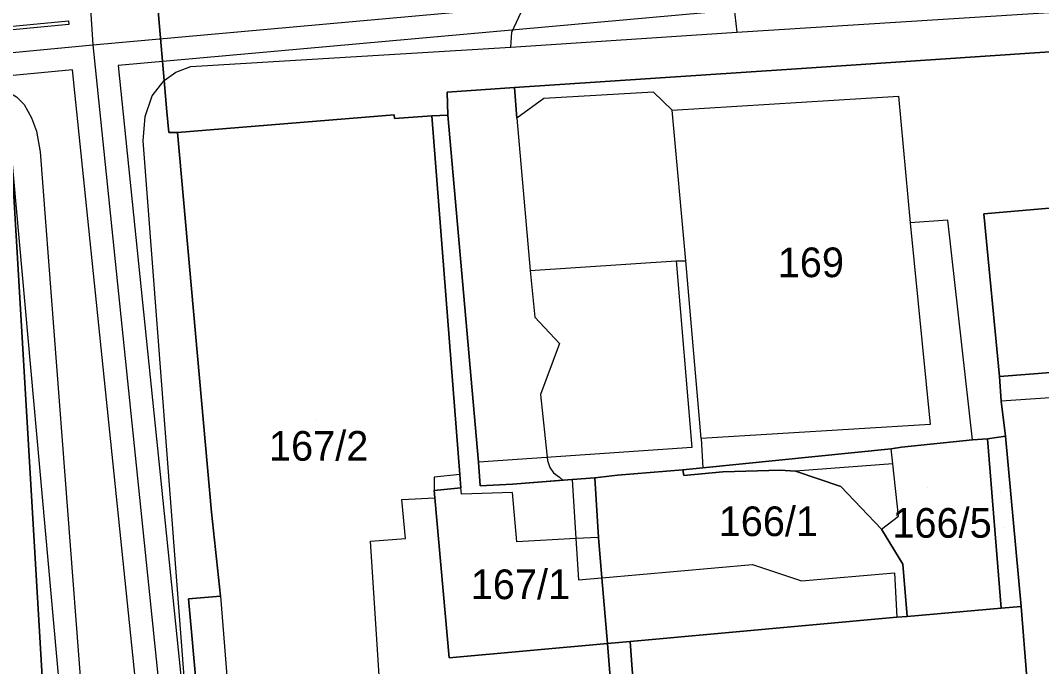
# Model space of a CAD drawing. Extents: x -263423 to -261326, y -1240067 to -1237864.
# Drawn here: x -262906.4 to -262837.6, y -1239995.6 to -1239952.1 of the extents above; entities that cross this region are included whole.
import ezdxf

# ---------------------------------------------------------------- set-up
doc = ezdxf.new("R2010")
doc.units = 0
for name, color, linetype in [('body_kn', 7, 'Continuous'), ('kladpar_druhypozemkov', 7, 'Continuous'), ('kladpar_hranice', 7, 'Continuous'), ('kladpar_parcelnecisla', 7, 'Continuous'), ('kladpar_plochy', 7, 'Continuous'), ('kladpar_sipky', 7, 'Continuous'), ('tarchy_linie', 7, 'Continuous'), ('zappar_hrandruhpozemk', 7, 'Continuous')]:
    doc.layers.add(name, color=color, linetype=linetype)

msp = doc.modelspace()

# ---------------------------------------------------------------- linework, layer by layer
at = {"layer": 'body_kn'}
for p, q in [((-262903.16, -1239952.09), (-262903.16, -1239952.09)), ((-262903.16, -1239952.09), (-262903.16, -1239952.09)), ((-262903.14, -1239952.33), (-262903.14, -1239952.33)), ((-262873.29, -1239952.85), (-262873.29, -1239952.85)), ((-262858.12, -1239952.85), (-262858.12, -1239952.85)), ((-262858.12, -1239952.85), (-262858.12, -1239952.85)), ((-262901.51, -1239953.72), (-262901.51, -1239953.72)), ((-262873.36, -1239953.87), (-262873.36, -1239953.87)), ((-262873.36, -1239953.87), (-262873.36, -1239953.87)), ((-262902.88, -1239955.4), (-262902.88, -1239955.4)), ((-262899.82, -1239955.11), (-262899.82, -1239955.11)), ((-262894.91, -1239955.17), (-262894.91, -1239955.17)), ((-262854.44, -1239955.35), (-262854.44, -1239955.35)), ((-262854.44, -1239955.35), (-262854.44, -1239955.35)), ((-262896.7, -1239956.12), (-262896.7, -1239956.12)), ((-262896.7, -1239956.12), (-262896.7, -1239956.12)), ((-262895.93, -1239955.55), (-262895.93, -1239955.55)), ((-262877.64, -1239956.91), (-262877.64, -1239956.91)), ((-262877.64, -1239956.91), (-262877.64, -1239956.91)), ((-262873.11, -1239956.58), (-262873.11, -1239956.58)), ((-262863.75, -1239956.9), (-262863.75, -1239956.9)), ((-262897.53, -1239957.14), (-262897.53, -1239957.14)), ((-262871.14, -1239957.32), (-262871.14, -1239957.32)), ((-262847.24, -1239957.17), (-262847.24, -1239957.17)), ((-262906.14, -1239957.73), (-262906.14, -1239957.73)), ((-262896.52, -1239958.22), (-262896.52, -1239958.22)), ((-262862.48, -1239958.12), (-262862.48, -1239958.12)), ((-262905.64, -1239958.63), (-262905.64, -1239958.63)), ((-262897.99, -1239958.54), (-262897.99, -1239958.54)), ((-262881.22, -1239958.42), (-262881.22, -1239958.42)), ((-262881.22, -1239958.42), (-262881.22, -1239958.42)), ((-262881.2, -1239958.68), (-262881.2, -1239958.68)), ((-262878.67, -1239958.5), (-262878.67, -1239958.5)), ((-262877.59, -1239958.44), (-262877.59, -1239958.44)), ((-262872.94, -1239958.65), (-262872.94, -1239958.65)), ((-262872.94, -1239958.65), (-262872.94, -1239958.65)), ((-262905.32, -1239959.52), (-262905.32, -1239959.52)), ((-262896.4, -1239959.63), (-262896.4, -1239959.63)), ((-262895.82, -1239959.63), (-262895.82, -1239959.63)), ((-262898.12, -1239960.19), (-262898.12, -1239960.19)), ((-262905.07, -1239960.93), (-262905.07, -1239960.93)), ((-262841.48, -1239965.1), (-262841.48, -1239965.1)), ((-262846.45, -1239965.71), (-262846.45, -1239965.71)), ((-262843.9, -1239965.53), (-262843.9, -1239965.53)), ((-262862.21, -1239968.26), (-262862.21, -1239968.26)), ((-262861.57, -1239968.26), (-262861.57, -1239968.26)), ((-262861.57, -1239968.26), (-262861.57, -1239968.26)), ((-262872.05, -1239968.91), (-262872.05, -1239968.91)), ((-262872.05, -1239968.91), (-262872.05, -1239968.91)), ((-262871.73, -1239972.06), (-262871.73, -1239972.06)), ((-262870.08, -1239973.83), (-262870.08, -1239973.83)), ((-262840.44, -1239976.07), (-262840.44, -1239976.07)), ((-262871.35, -1239977.27), (-262871.35, -1239977.27)), ((-262840.32, -1239977.72), (-262840.32, -1239977.72)), ((-262845.11, -1239979.3), (-262845.11, -1239979.3)), ((-262860.54, -1239980.25), (-262860.54, -1239980.25)), ((-262860.54, -1239980.25), (-262860.54, -1239980.25)), ((-262841.23, -1239980.27), (-262841.23, -1239980.27)), ((-262840.02, -1239980.08), (-262840.02, -1239980.08)), ((-262861.17, -1239980.84), (-262861.17, -1239980.84)), ((-262847.73, -1239980.94), (-262847.73, -1239980.94)), ((-262847.03, -1239980.82), (-262847.03, -1239980.82)), ((-262842.25, -1239980.33), (-262842.25, -1239980.33)), ((-262842.25, -1239980.33), (-262842.25, -1239980.33)), ((-262875.54, -1239981.83), (-262875.54, -1239981.83)), ((-262870.89, -1239981.73), (-262870.89, -1239981.73)), ((-262870.73, -1239982.19), (-262870.73, -1239982.19)), ((-262861.76, -1239982.35), (-262861.76, -1239982.35)), ((-262860.42, -1239982.22), (-262860.42, -1239982.22)), ((-262855.2, -1239982.37), (-262855.2, -1239982.37)), ((-262855.2, -1239982.37), (-262855.2, -1239982.37)), ((-262847.61, -1239981.96), (-262847.61, -1239981.96)), ((-262878.53, -1239982.84), (-262878.53, -1239982.84)), ((-262876.8, -1239982.66), (-262876.8, -1239982.66)), ((-262876.8, -1239982.66), (-262876.8, -1239982.66)), ((-262870.47, -1239982.55), (-262870.47, -1239982.55)), ((-262870.08, -1239982.86), (-262870.08, -1239982.86)), ((-262869.22, -1239983.01), (-262869.22, -1239983.01)), ((-262869.22, -1239983.01), (-262869.22, -1239983.01)), ((-262867.69, -1239982.89), (-262867.69, -1239982.89)), ((-262866.16, -1239982.71), (-262866.16, -1239982.71)), ((-262861.7, -1239982.73), (-262861.7, -1239982.73)), ((-262859.08, -1239982.48), (-262859.08, -1239982.48)), ((-262856.73, -1239982.43), (-262856.73, -1239982.43)), ((-262854.18, -1239982.44), (-262854.18, -1239982.44)), ((-262878.53, -1239983.74), (-262878.53, -1239983.74)), ((-262876.72, -1239983.56), (-262876.72, -1239983.56)), ((-262875.41, -1239983.43), (-262875.41, -1239983.43)), ((-262873.24, -1239983.31), (-262873.24, -1239983.31)), ((-262869.84, -1239983.06), (-262869.84, -1239983.06)), ((-262851.12, -1239983.48), (-262851.12, -1239983.48)), ((-262880.7, -1239984.36), (-262880.7, -1239984.36)), ((-262878.47, -1239984.25), (-262878.47, -1239984.25)), ((-262876.68, -1239984), (-262876.68, -1239984)), ((-262873.24, -1239983.89), (-262873.24, -1239983.89)), ((-262893.52, -1239985.2), (-262893.52, -1239985.2)), ((-262847.24, -1239985.47), (-262847.24, -1239985.47)), ((-262848.39, -1239986.36), (-262848.39, -1239986.36)), ((-262848.39, -1239986.36), (-262848.39, -1239986.36)), ((-262882.82, -1239987.16), (-262882.82, -1239987.16)), ((-262880.46, -1239986.98), (-262880.46, -1239986.98)), ((-262868.97, -1239986.99), (-262868.97, -1239986.99)), ((-262868.97, -1239986.99), (-262868.97, -1239986.99)), ((-262867.45, -1239986.91), (-262867.45, -1239986.91)), ((-262867.45, -1239986.91), (-262867.45, -1239986.91)), ((-262872.94, -1239987.2), (-262872.94, -1239987.2)), ((-262857.07, -1239988.74), (-262857.07, -1239988.74)), ((-262846.94, -1239988.72), (-262846.94, -1239988.72)), ((-262868.8, -1239989.77), (-262868.8, -1239989.77)), ((-262867.22, -1239989.63), (-262867.22, -1239989.63)), ((-262867.22, -1239989.63), (-262867.22, -1239989.63)), ((-262853.76, -1239989.84), (-262853.76, -1239989.84)), ((-262847.51, -1239989.29), (-262847.51, -1239989.29)), ((-262895.07, -1239991.06), (-262895.07, -1239991.06)), ((-262892.91, -1239990.88), (-262892.91, -1239990.88)), ((-262892.91, -1239990.88), (-262892.91, -1239990.88)), ((-262840.32, -1239991.68), (-262840.32, -1239991.68)), ((-262838.98, -1239991.56), (-262838.98, -1239991.56)), ((-262838.98, -1239991.56), (-262838.98, -1239991.56)), ((-262847.34, -1239992.29), (-262847.34, -1239992.29)), ((-262847.34, -1239992.29), (-262847.34, -1239992.29)), ((-262846.64, -1239992.23), (-262846.64, -1239992.23)), ((-262866.85, -1239994.05), (-262866.85, -1239994.05)), ((-262865.32, -1239993.93), (-262865.32, -1239993.93)), ((-262877.5, -1239995.02), (-262877.5, -1239995.02))]:
    msp.add_line(p, q, dxfattribs=at)
at = {"layer": 'kladpar_druhypozemkov'}
for p, q in [((-262853.98, -1239966.97), (-262853.98, -1239966.97)), ((-262886.48, -1239979.04), (-262886.48, -1239979.04)), ((-262845.26, -1239983.53), (-262845.26, -1239983.53)), ((-262840.38, -1239983.87), (-262840.38, -1239983.87)), ((-262856.3, -1239984.84), (-262856.3, -1239984.84)), ((-262873.08, -1239988.87), (-262873.08, -1239988.87))]:
    msp.add_line(p, q, dxfattribs=at)
at = {"layer": 'kladpar_hranice'}
for points in [[(-262897.73, -1239944.39), (-262896.7, -1239956.12), (-262896.52, -1239958.22), (-262896.4, -1239959.63), (-262895.82, -1239959.63), (-262893.52, -1239985.2), (-262892.91, -1239990.88), (-262895.07, -1239991.06), (-262893.93, -1240003.7), (-262891.76, -1240003.57), (-262891.13, -1240005.79), (-262889.92, -1240007.83), (-262888, -1240009.03), (-262886.09, -1240009.54), (-262882.65, -1240009.16), (-262882.53, -1240009.86), (-262894.24, -1240011.13), (-262901.19, -1240011.76), (-262902.4, -1240011.85), (-262903.67, -1240011.95), (-262904.89, -1239997.06), (-262907.05, -1239960.47)], [(-262819.92, -1239947.16), (-262817.97, -1239952.9), (-262854.44, -1239955.35), (-262873.11, -1239956.58), (-262877.64, -1239956.91), (-262877.59, -1239958.44), (-262878.67, -1239958.5), (-262881.2, -1239958.68), (-262881.22, -1239958.42), (-262895.82, -1239959.63), (-262896.4, -1239959.63), (-262896.52, -1239958.22), (-262896.7, -1239956.12), (-262897.73, -1239944.39)], [(-262854.44, -1239955.35), (-262817.97, -1239952.9), (-262814.77, -1239962.79), (-262841.48, -1239965.1), (-262840.44, -1239976.07), (-262840.32, -1239977.72), (-262840.02, -1239980.08), (-262841.23, -1239980.27), (-262842.25, -1239980.33), (-262847.03, -1239980.82), (-262847.73, -1239980.94), (-262860.42, -1239982.22), (-262861.76, -1239982.35), (-262866.16, -1239982.71), (-262867.69, -1239982.89), (-262869.22, -1239983.01), (-262873.24, -1239983.31), (-262875.41, -1239983.43), (-262875.54, -1239981.83), (-262877.59, -1239958.44), (-262877.64, -1239956.91), (-262873.11, -1239956.58), (-262854.44, -1239955.35)], [(-262881.22, -1239958.42), (-262881.2, -1239958.68), (-262878.67, -1239958.5), (-262876.8, -1239982.66), (-262876.72, -1239983.56), (-262878.53, -1239983.74), (-262878.47, -1239984.25), (-262877.5, -1239995.02), (-262866.85, -1239994.05), (-262866.61, -1239996.92), (-262865.84, -1240007.96), (-262882.53, -1240009.86), (-262882.65, -1240009.16), (-262886.09, -1240009.54), (-262888, -1240009.03), (-262889.92, -1240007.83), (-262891.13, -1240005.79), (-262891.76, -1240003.57), (-262893.93, -1240003.7), (-262895.07, -1239991.06), (-262892.91, -1239990.88), (-262893.52, -1239985.2), (-262895.82, -1239959.63), (-262881.22, -1239958.42)], [(-262869.22, -1239983.01), (-262867.69, -1239982.89), (-262867.45, -1239986.91), (-262867.22, -1239989.63), (-262866.85, -1239994.05), (-262877.5, -1239995.02), (-262878.47, -1239984.25), (-262878.53, -1239983.74), (-262876.72, -1239983.56), (-262876.8, -1239982.66), (-262878.67, -1239958.5), (-262877.59, -1239958.44), (-262875.54, -1239981.83), (-262875.41, -1239983.43), (-262873.24, -1239983.31), (-262869.22, -1239983.01)], [(-262907.05, -1239960.47), (-262904.89, -1239997.06), (-262921.76, -1239998.46), (-262923.47, -1239968.3), (-262925.45, -1239968.35), (-262925.57, -1239966.7), (-262925.75, -1239964.4), (-262925.86, -1239962.17), (-262923.86, -1239962.02), (-262907.05, -1239960.47)], [(-262814.77, -1239962.79), (-262812.32, -1239970.52), (-262822.07, -1239971.18), (-262821.96, -1239974.62), (-262840.44, -1239976.07), (-262841.48, -1239965.1), (-262814.77, -1239962.79)], [(-262837.56, -1240008.91), (-262837.63, -1240008.72), (-262837.82, -1240005.99), (-262838.98, -1239991.56), (-262840.02, -1239980.08), (-262840.32, -1239977.72), (-262840.44, -1239976.07), (-262821.96, -1239974.62)], [(-262842.25, -1239980.33), (-262841.23, -1239980.27), (-262840.32, -1239991.68), (-262846.64, -1239992.23), (-262846.94, -1239988.72), (-262848.39, -1239986.36), (-262851.12, -1239983.48), (-262854.18, -1239982.44), (-262855.2, -1239982.37), (-262856.73, -1239982.43), (-262859.08, -1239982.48), (-262861.7, -1239982.73), (-262861.76, -1239982.35), (-262860.42, -1239982.22), (-262847.73, -1239980.94), (-262847.03, -1239980.82), (-262842.25, -1239980.33)], [(-262838.98, -1239991.56), (-262840.32, -1239991.68), (-262841.23, -1239980.27), (-262840.02, -1239980.08), (-262838.98, -1239991.56)], [(-262855.2, -1239982.37), (-262854.18, -1239982.44), (-262851.12, -1239983.48), (-262848.39, -1239986.36), (-262846.94, -1239988.72), (-262846.64, -1239992.23), (-262847.34, -1239992.29), (-262865.32, -1239993.93), (-262866.85, -1239994.05), (-262867.22, -1239989.63), (-262867.45, -1239986.91), (-262867.69, -1239982.89), (-262866.16, -1239982.71), (-262861.76, -1239982.35), (-262861.7, -1239982.73), (-262859.08, -1239982.48), (-262856.73, -1239982.43), (-262855.2, -1239982.37)], [(-262847.34, -1239992.29), (-262846.64, -1239992.23), (-262840.32, -1239991.68), (-262838.98, -1239991.56), (-262837.82, -1240005.99), (-262838.84, -1240006.05), (-262839.67, -1240006.12), (-262844.38, -1240006.5), (-262851.7, -1240007), (-262864.31, -1240007.89), (-262865.32, -1239993.93), (-262847.34, -1239992.29)], [(-262864.31, -1240007.89), (-262865.84, -1240007.96), (-262866.61, -1239996.92), (-262866.85, -1239994.05), (-262865.32, -1239993.93), (-262864.31, -1240007.89)]]:
    msp.add_lwpolyline(points, dxfattribs=at)
at = {"layer": 'kladpar_plochy'}
for points in [[(-262897.73, -1239944.39), (-262896.7, -1239956.12), (-262896.52, -1239958.22), (-262896.4, -1239959.63), (-262895.82, -1239959.63), (-262893.52, -1239985.2), (-262892.91, -1239990.88), (-262895.07, -1239991.06), (-262893.93, -1240003.7), (-262891.76, -1240003.57), (-262891.13, -1240005.79), (-262889.92, -1240007.83), (-262888, -1240009.03), (-262886.09, -1240009.54), (-262882.65, -1240009.16), (-262882.53, -1240009.86), (-262894.24, -1240011.13), (-262901.19, -1240011.76), (-262902.4, -1240011.85), (-262903.67, -1240011.95), (-262904.89, -1239997.06), (-262907.05, -1239960.47)], [(-262819.92, -1239947.16), (-262817.97, -1239952.9), (-262854.44, -1239955.35), (-262873.11, -1239956.58), (-262877.64, -1239956.91), (-262877.59, -1239958.44), (-262878.67, -1239958.5), (-262881.2, -1239958.68), (-262881.22, -1239958.42), (-262895.82, -1239959.63), (-262896.4, -1239959.63), (-262896.52, -1239958.22), (-262896.7, -1239956.12), (-262897.73, -1239944.39)], [(-262837.56, -1240008.91), (-262837.63, -1240008.72), (-262837.82, -1240005.99), (-262838.98, -1239991.56), (-262840.02, -1239980.08), (-262840.32, -1239977.72), (-262840.44, -1239976.07), (-262821.96, -1239974.62)]]:
    msp.add_lwpolyline(points, dxfattribs=at)
for points in [[(-262854.44, -1239955.35), (-262817.97, -1239952.9), (-262814.77, -1239962.79), (-262841.48, -1239965.1), (-262840.44, -1239976.07), (-262840.32, -1239977.72), (-262840.02, -1239980.08), (-262841.23, -1239980.27), (-262842.25, -1239980.33), (-262847.03, -1239980.82), (-262847.73, -1239980.94), (-262860.42, -1239982.22), (-262861.76, -1239982.35), (-262866.16, -1239982.71), (-262867.69, -1239982.89), (-262869.22, -1239983.01), (-262873.24, -1239983.31), (-262875.41, -1239983.43), (-262875.54, -1239981.83), (-262877.59, -1239958.44), (-262877.64, -1239956.91), (-262873.11, -1239956.58)], [(-262881.22, -1239958.42), (-262881.2, -1239958.68), (-262878.67, -1239958.5), (-262876.8, -1239982.66), (-262876.72, -1239983.56), (-262878.53, -1239983.74), (-262878.47, -1239984.25), (-262877.5, -1239995.02), (-262866.85, -1239994.05), (-262866.61, -1239996.92), (-262865.84, -1240007.96), (-262882.53, -1240009.86), (-262882.65, -1240009.16), (-262886.09, -1240009.54), (-262888, -1240009.03), (-262889.92, -1240007.83), (-262891.13, -1240005.79), (-262891.76, -1240003.57), (-262893.93, -1240003.7), (-262895.07, -1239991.06), (-262892.91, -1239990.88), (-262893.52, -1239985.2), (-262895.82, -1239959.63)], [(-262869.22, -1239983.01), (-262867.69, -1239982.89), (-262867.45, -1239986.91), (-262867.22, -1239989.63), (-262866.85, -1239994.05), (-262877.5, -1239995.02), (-262878.47, -1239984.25), (-262878.53, -1239983.74), (-262876.72, -1239983.56), (-262876.8, -1239982.66), (-262878.67, -1239958.5), (-262877.59, -1239958.44), (-262875.54, -1239981.83), (-262875.41, -1239983.43), (-262873.24, -1239983.31)], [(-262907.05, -1239960.47), (-262904.89, -1239997.06), (-262921.76, -1239998.46), (-262923.47, -1239968.3), (-262925.45, -1239968.35), (-262925.57, -1239966.7), (-262925.75, -1239964.4), (-262925.86, -1239962.17), (-262923.86, -1239962.02)], [(-262814.77, -1239962.79), (-262812.32, -1239970.52), (-262822.07, -1239971.18), (-262821.96, -1239974.62), (-262840.44, -1239976.07), (-262841.48, -1239965.1)], [(-262842.25, -1239980.33), (-262841.23, -1239980.27), (-262840.32, -1239991.68), (-262846.64, -1239992.23), (-262846.94, -1239988.72), (-262848.39, -1239986.36), (-262851.12, -1239983.48), (-262854.18, -1239982.44), (-262855.2, -1239982.37), (-262856.73, -1239982.43), (-262859.08, -1239982.48), (-262861.7, -1239982.73), (-262861.76, -1239982.35), (-262860.42, -1239982.22), (-262847.73, -1239980.94), (-262847.03, -1239980.82)], [(-262838.98, -1239991.56), (-262840.32, -1239991.68), (-262841.23, -1239980.27), (-262840.02, -1239980.08)], [(-262855.2, -1239982.37), (-262854.18, -1239982.44), (-262851.12, -1239983.48), (-262848.39, -1239986.36), (-262846.94, -1239988.72), (-262846.64, -1239992.23), (-262847.34, -1239992.29), (-262865.32, -1239993.93), (-262866.85, -1239994.05), (-262867.22, -1239989.63), (-262867.45, -1239986.91), (-262867.69, -1239982.89), (-262866.16, -1239982.71), (-262861.76, -1239982.35), (-262861.7, -1239982.73), (-262859.08, -1239982.48), (-262856.73, -1239982.43)], [(-262847.34, -1239992.29), (-262846.64, -1239992.23), (-262840.32, -1239991.68), (-262838.98, -1239991.56), (-262837.82, -1240005.99), (-262838.84, -1240006.05), (-262839.67, -1240006.12), (-262844.38, -1240006.5), (-262851.7, -1240007), (-262864.31, -1240007.89), (-262865.32, -1239993.93)], [(-262864.31, -1240007.89), (-262865.84, -1240007.96), (-262866.61, -1239996.92), (-262866.85, -1239994.05), (-262865.32, -1239993.93)]]:
    msp.add_lwpolyline(points, close=True, dxfattribs=at)
at = {"layer": 'kladpar_sipky'}
msp.add_line((-262840.11, -1239986.21), (-262840.11, -1239986.21), dxfattribs=at)
at = {"layer": 'tarchy_linie'}
for points in [[(-262910.44, -1239816.22), (-262901.51, -1239953.72), (-262895.59, -1240011.25)], [(-262709.98, -1239889.68), (-262759.08, -1239904.49), (-262813.11, -1239920.03), (-262808.03, -1239945.12), (-262788.66, -1240001.16), (-262790.25, -1240001.33), (-262791.83, -1240001.51), (-262810.61, -1239947.07), (-262812.11, -1239947.21), (-262801.24, -1239976.32), (-262791.84, -1240001.51), (-262793.53, -1240001.71), (-262795.23, -1240001.9), (-262804.34, -1239977.48), (-262815.51, -1239947.51), (-262899.82, -1239955.11), (-262894.05, -1240011.11), (-262894.24, -1240011.13), (-262895.59, -1240011.25), (-262897.12, -1240011.39), (-262902.88, -1239955.4), (-263031.17, -1239967.61)], [(-263142, -1239976.35), (-263032.77, -1239966.22), (-262901.51, -1239953.72), (-262809.55, -1239945.43)], [(-262903.16, -1239952.09), (-262903.14, -1239952.33), (-263031.35, -1239964.54), (-263031.39, -1239963.84), (-262987.33, -1239959.86), (-262956.35, -1239956.97), (-262944.73, -1239956.07), (-262903.16, -1239952.09)], [(-262877.64, -1239956.91), (-262873.11, -1239956.58), (-262872.94, -1239958.65), (-262872.05, -1239968.91), (-262871.73, -1239972.06), (-262870.08, -1239973.83), (-262871.35, -1239977.27), (-262870.89, -1239981.73), (-262870.73, -1239982.19), (-262870.47, -1239982.55), (-262870.08, -1239982.86), (-262869.84, -1239983.06), (-262873.24, -1239983.31), (-262875.41, -1239983.43), (-262875.54, -1239981.83), (-262877.59, -1239958.44), (-262877.64, -1239956.91)]]:
    msp.add_lwpolyline(points, dxfattribs=at)
at = {"layer": 'zappar_hrandruhpozemk'}
for p, q in [((-262858.8, -1239947.24), (-262858.12, -1239952.85)), ((-262858.12, -1239952.85), (-262830.52, -1239951.13)), ((-262872.94, -1239958.65), (-262873.11, -1239956.58)), ((-262862.48, -1239958.12), (-262847.24, -1239957.17)), ((-262861.57, -1239968.26), (-262862.48, -1239958.12)), ((-262894.24, -1240011.13), (-262898.12, -1239960.19)), ((-262903.47, -1240000.07), (-262907.05, -1239960.47)), ((-262905.07, -1239960.93), (-262901.19, -1240011.76)), ((-262872.05, -1239968.91), (-262862.21, -1239968.26)), ((-262862.21, -1239968.26), (-262861.57, -1239968.26)), ((-262860.54, -1239980.25), (-262861.57, -1239968.26)), ((-262820.24, -1239976.35), (-262840.32, -1239977.72)), ((-262845.11, -1239979.3), (-262860.54, -1239980.25)), ((-262860.54, -1239980.25), (-262860.42, -1239982.22)), ((-262847.61, -1239981.96), (-262847.73, -1239980.94)), ((-262847.61, -1239981.96), (-262854.18, -1239982.44)), ((-262847.24, -1239985.47), (-262847.61, -1239981.96)), ((-262876.8, -1239982.66), (-262878.53, -1239982.84)), ((-262878.53, -1239982.84), (-262878.53, -1239983.74)), ((-262869.22, -1239983.01), (-262868.97, -1239986.99)), ((-262848.39, -1239986.36), (-262847.24, -1239985.47)), ((-262882.22, -1239996.21), (-262882.82, -1239987.16)), ((-262868.97, -1239986.99), (-262868.8, -1239989.77)), ((-262867.22, -1239989.63), (-262857.07, -1239988.74)), ((-262868.8, -1239989.77), (-262867.22, -1239989.63)), ((-262892.91, -1239990.88), (-262892.48, -1239996.23))]:
    msp.add_line(p, q, dxfattribs=at)
for points in [[(-262873.36, -1239953.87), (-262873.29, -1239952.85), (-262872.65, -1239951.51), (-262871.37, -1239950.24), (-262869.83, -1239949.17), (-262867.34, -1239948.16)], [(-262896.7, -1239956.12), (-262895.93, -1239955.55), (-262894.91, -1239955.17), (-262873.36, -1239953.87), (-262858.12, -1239952.85)], [(-262898.12, -1239960.19), (-262897.99, -1239958.54), (-262897.53, -1239957.14), (-262896.7, -1239956.12)], [(-262907.29, -1239956.84), (-262906.65, -1239957.22), (-262906.14, -1239957.73), (-262905.64, -1239958.63), (-262905.32, -1239959.52), (-262905.07, -1239960.93)], [(-262862.48, -1239958.12), (-262863.75, -1239956.9), (-262871.14, -1239957.32), (-262872.94, -1239958.65), (-262872.05, -1239968.91)], [(-262847.24, -1239957.17), (-262846.45, -1239965.71), (-262845.11, -1239979.3)], [(-262842.25, -1239980.33), (-262843.9, -1239965.53), (-262846.45, -1239965.71)], [(-262862.21, -1239968.26), (-262861.17, -1239980.84), (-262875.54, -1239981.83)], [(-262872.94, -1239987.2), (-262873.24, -1239983.89), (-262876.68, -1239984), (-262876.72, -1239983.56)], [(-262882.82, -1239987.16), (-262880.46, -1239986.98), (-262880.7, -1239984.36), (-262878.47, -1239984.25)], [(-262867.45, -1239986.91), (-262868.97, -1239986.99), (-262872.94, -1239987.2)], [(-262857.07, -1239988.74), (-262853.76, -1239989.84), (-262847.51, -1239989.29), (-262847.34, -1239992.29)]]:
    msp.add_lwpolyline(points, dxfattribs=at)

# ---------------------------------------------------------------- texts
at = {"layer": 'kladpar_parcelnecisla'}
for s, p in [('169', (-262855.37, -1239969.37)), ('167/2', (-262889.649, -1239981.74)), ('166/1', (-262859.35, -1239986.82)), ('166/5', (-262847.645, -1239986.93)), ('167/1', (-262876.053, -1239991.07))]:
    msp.add_text(s, height=2, dxfattribs=at).set_placement(p)

doc.saveas('drawing.dxf')
